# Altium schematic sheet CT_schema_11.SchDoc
size 742 x 377 mm
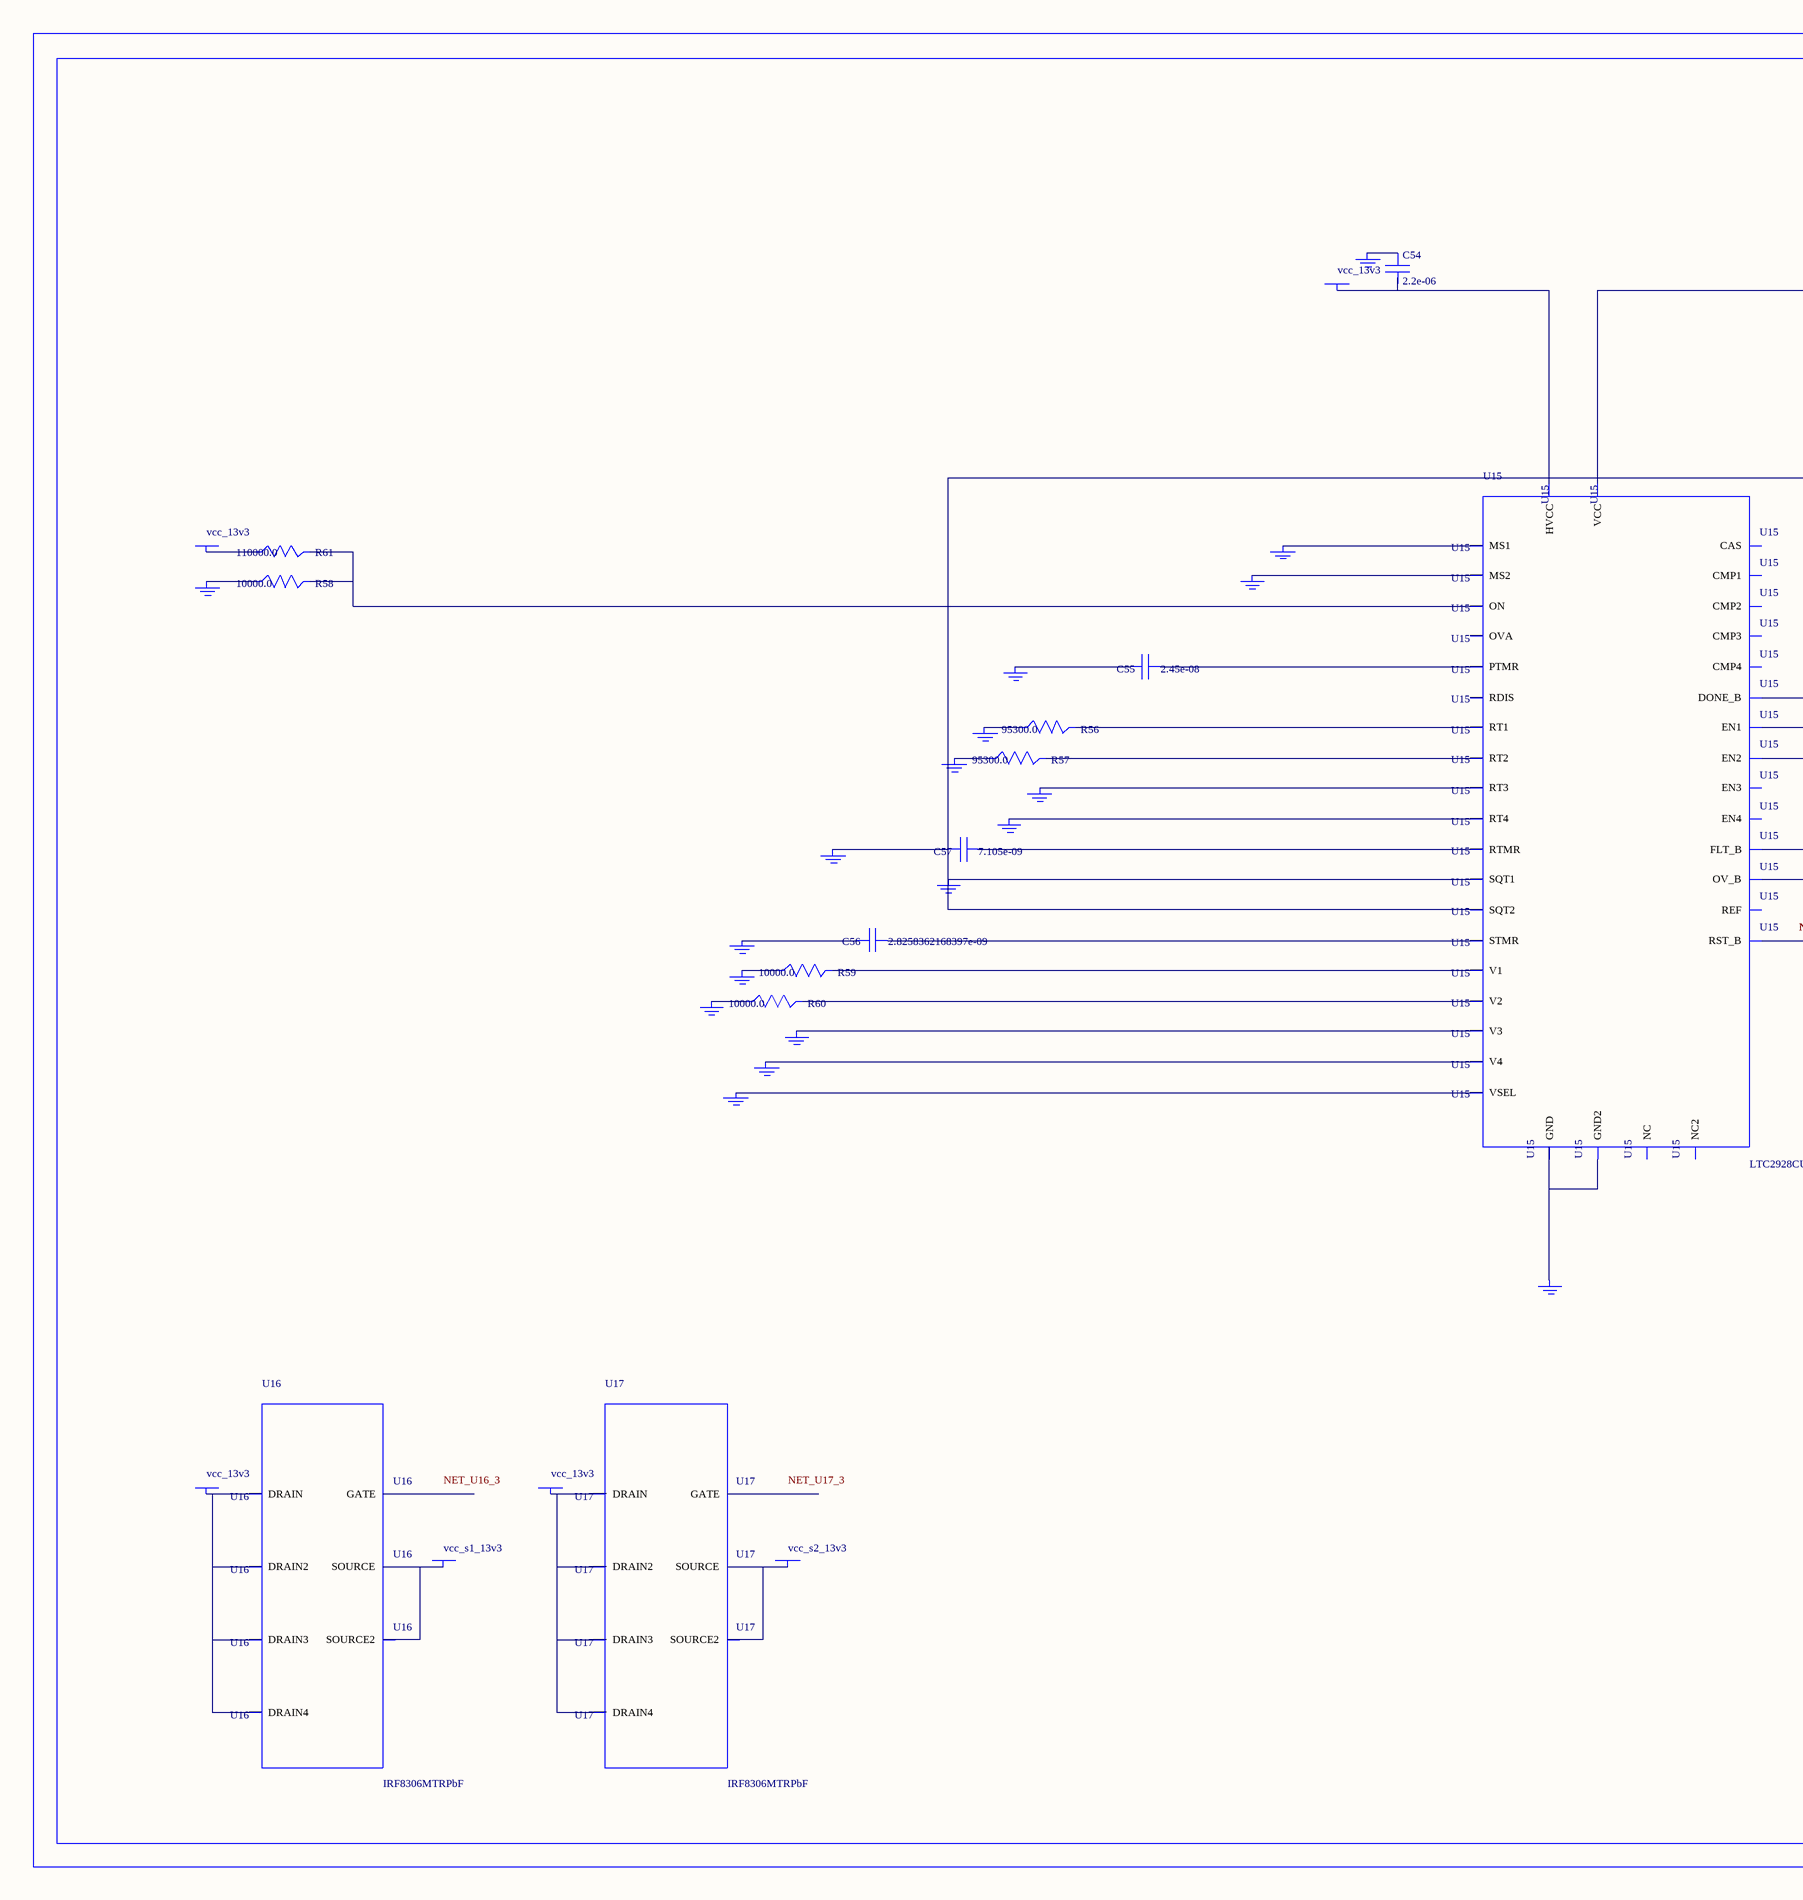
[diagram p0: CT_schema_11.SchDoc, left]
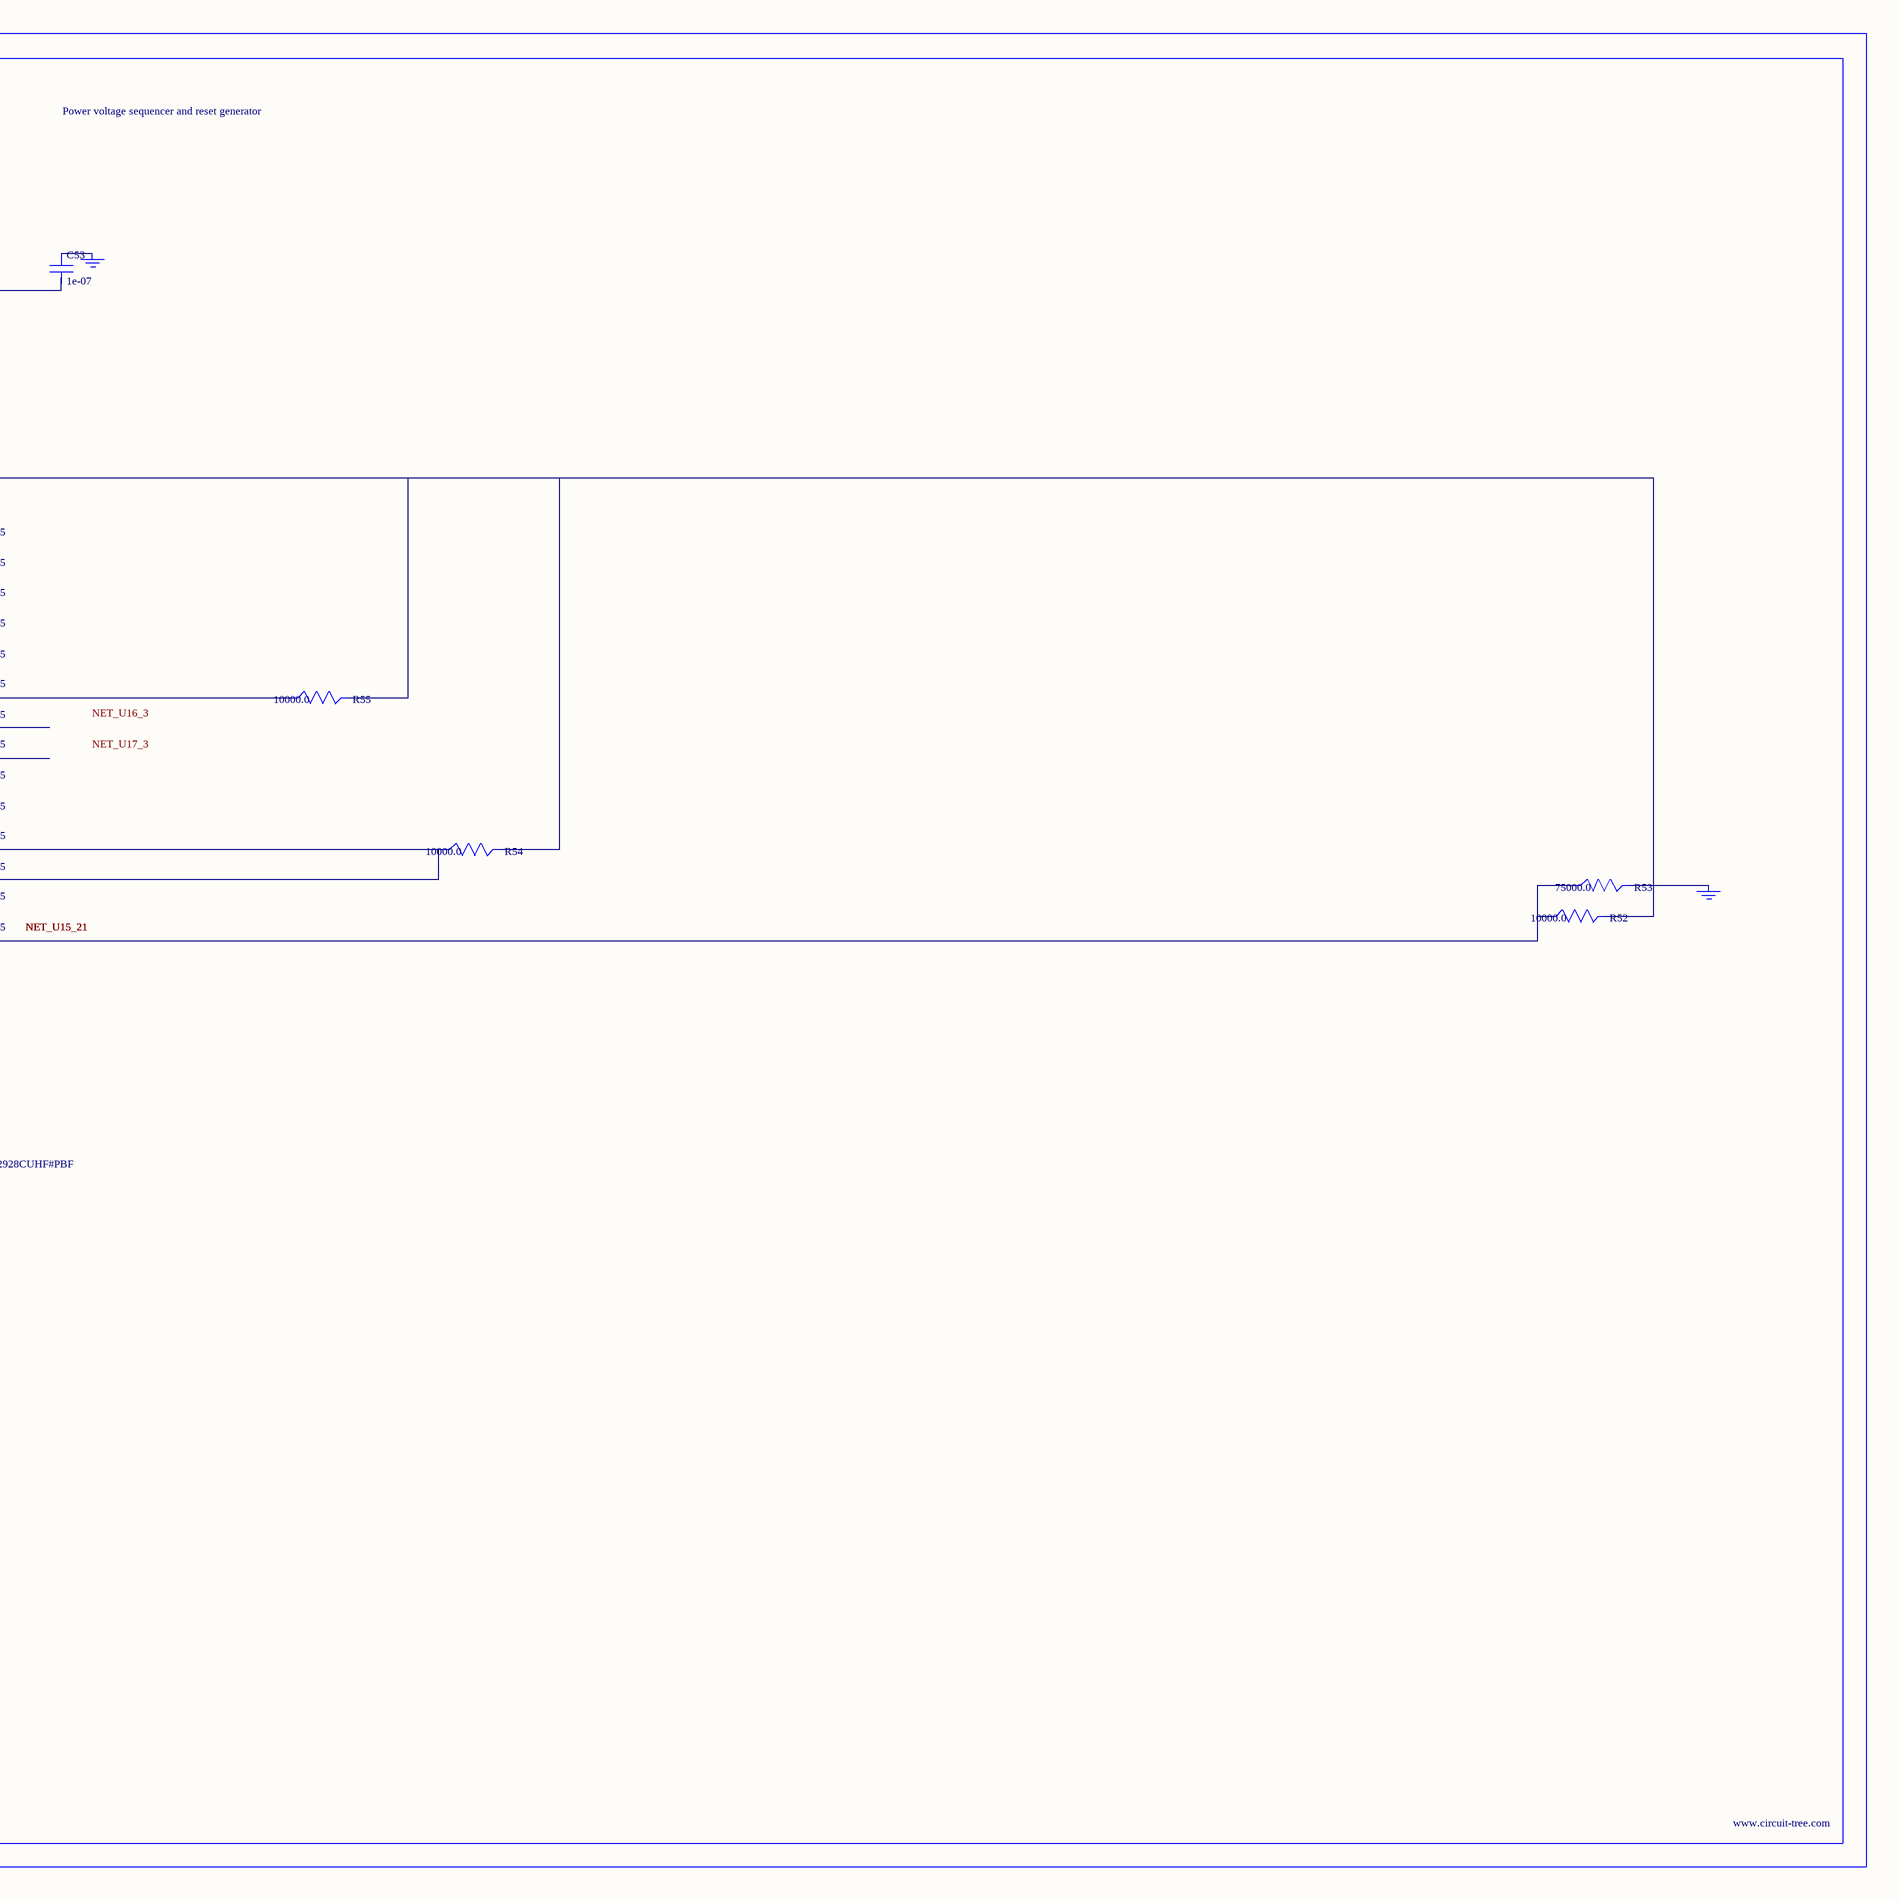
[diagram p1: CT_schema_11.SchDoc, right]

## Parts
BORDER10  (no value)
C53  1e-07  [C0402]
C54  2.2e-06  [C0603]
C55  2.45e-08  [R0603]
C56  2.8258362168397e-09  [R0603]
C57  7.105e-09  [R0603]
GND_INSTANCE_10_0  (no value)
GND_INSTANCE_10_1  (no value)
GND_INSTANCE_10_2  (no value)
GND_INSTANCE_10_3  (no value)
GND_INSTANCE_10_4  (no value)
GND_INSTANCE_10_5  (no value)
GND_INSTANCE_10_6  (no value)
GND_INSTANCE_10_7  (no value)
GND_INSTANCE_10_8  (no value)
GND_INSTANCE_10_9  (no value)
GND_INSTANCE_10_10  (no value)
GND_INSTANCE_10_11  (no value)
GND_INSTANCE_10_12  (no value)
GND_INSTANCE_10_13  (no value)
GND_INSTANCE_10_14  (no value)
GND_INSTANCE_10_15  (no value)
GND_INSTANCE_10_16  (no value)
GND_INSTANCE_10_17  (no value)
GND_INSTANCE_10_18  (no value)
GND_INSTANCE_10_19  (no value)
POWER_INSTANCE_10_0  vcc_13v3
POWER_INSTANCE_10_1  vcc_13v3
POWER_INSTANCE_10_2  vcc_13v3
POWER_INSTANCE_10_3  vcc_s1_13v3
POWER_INSTANCE_10_4  vcc_13v3
POWER_INSTANCE_10_5  vcc_s2_13v3
R52  10000.0  [R0603]
R53  75000.0  [R0603]
R54  10000.0  [R0603]
R55  10000.0  [R0603]
R56  95300.0  [R0603]
R57  95300.0  [R0603]
R58  10000.0  [R0603]
R59  10000.0  [R0603]
R60  10000.0  [R0603]
R61  110000.0  [R0603]
U15  LTC2928CUHF#PBF  [QFN-38_UHF]
U16  IRF8306MTRPbF  [IRF8306MTRPBF]
U17  IRF8306MTRPbF  [IRF8306MTRPBF]

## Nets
NetC53_1: C53.1 GND_INSTANCE_10_10.0(GND)
NetC53_2: C53.2 C57.2 GND_INSTANCE_10_5.0(GND) GND_INSTANCE_10_15.0(GND) R52.2 R54.2 R55.2 U15.10(SQT1) U15.11(SQT2) U15.22(VCC)
NetC54_1: C54.1 GND_INSTANCE_10_11.0(GND)
NetC54_2: C54.2 POWER_INSTANCE_10_1.0(PWR) U15.23(HVCC)
NetC55_1: C55.1 U15.27(PTMR)
NetC55_2: C55.2 GND_INSTANCE_10_14.0(GND)
NetC56_1: C56.1 U15.26(STMR)
NetC56_2: C56.2 GND_INSTANCE_10_13.0(GND)
NetC57_1: C57.1 U15.28(RTMR)
NetGND_INSTANCE_10_0_0: GND_INSTANCE_10_0.0(GND) R59.1
NetGND_INSTANCE_10_1_0: GND_INSTANCE_10_1.0(GND) R56.1
NetGND_INSTANCE_10_2_0: GND_INSTANCE_10_2.0(GND) R57.1
NetGND_INSTANCE_10_3_0: GND_INSTANCE_10_3.0(GND) U15.8(RT3)
NetGND_INSTANCE_10_4_0: GND_INSTANCE_10_4.0(GND) U15.9(RT4)
NetGND_INSTANCE_10_6_0: GND_INSTANCE_10_6.0(GND) U15.12(MS1)
NetGND_INSTANCE_10_7_0: GND_INSTANCE_10_7.0(GND) U15.13(MS2)
NetGND_INSTANCE_10_8_0: GND_INSTANCE_10_8.0(GND) R58.1
NetGND_INSTANCE_10_9_0: GND_INSTANCE_10_9.0(GND) R53.2
NetGND_INSTANCE_10_12_0: GND_INSTANCE_10_12.0(GND) U15.25(VSEL)
NetGND_INSTANCE_10_16_0: GND_INSTANCE_10_16.0(GND) U15.30(V4)
NetGND_INSTANCE_10_17_0: GND_INSTANCE_10_17.0(GND) U15.32(V3)
NetGND_INSTANCE_10_18_0: GND_INSTANCE_10_18.0(GND) R60.1
NetGND_INSTANCE_10_19_0: GND_INSTANCE_10_19.0(GND) U15.24(GND) U15.39(GND2)
NetPOWER_INSTANCE_10_0_0: POWER_INSTANCE_10_0.0(PWR) R61.1
NetPOWER_INSTANCE_10_2_0: POWER_INSTANCE_10_2.0(PWR) U16.1(DRAIN) U16.2(DRAIN2) U16.6(DRAIN3) U16.7(DRAIN4)
NetPOWER_INSTANCE_10_3_0: POWER_INSTANCE_10_3.0(PWR) U16.4(SOURCE) U16.5(SOURCE2)
NetPOWER_INSTANCE_10_4_0: POWER_INSTANCE_10_4.0(PWR) U17.1(DRAIN) U17.2(DRAIN2) U17.6(DRAIN3) U17.7(DRAIN4)
NetPOWER_INSTANCE_10_5_0: POWER_INSTANCE_10_5.0(PWR) U17.4(SOURCE) U17.5(SOURCE2)
NetR52_1: R52.1 R53.1 U15.21(RST_B)
NetR54_1: R54.1 U15.19(FLT_B) U15.20(OV_B)
NetR55_1: R55.1 U15.18(DONE_B)
NetR56_2: R56.2 U15.6(RT1)
NetR57_2: R57.2 U15.7(RT2)
NetR58_2: R58.2 R61.2 U15.16(ON)
NetR59_2: R59.2 U15.3(V1)
NetR60_2: R60.2 U15.38(V2)

Not connected (* = marked no-connect by the designer): U15 1(OVA) 2(EN1) 4(NC) 5(REF) 14(RDIS) 15(CAS) 17(NC2) 29(EN4) 31(EN3) 33(CMP3) 34(CMP4) 35(CMP1) 36(CMP2) 37(EN2); U16 3(GATE); U17 3(GATE)

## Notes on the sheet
- Labels drawn without touching a wire or pin: NET_U16_3, NET_U17_3

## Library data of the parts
BORDER10 = BORDER_PAGE10
C53 = C0402C104K3RACTU
C54 = GRM188R61H225KE1115D
C55 = C55
C56 = C56
C57 = C57
GND_INSTANCE_10_0-GND_INSTANCE_10_19 = GND
POWER_INSTANCE_10_0-POWER_INSTANCE_10_5 = PWR
R52 R54 R55 R58-R60 = RC0603JR-0710KL
R53 = RC0603JR-0775KL
R56 R57 = RC0603FR-0795K3L
R61 = RC0603JR-07110KL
